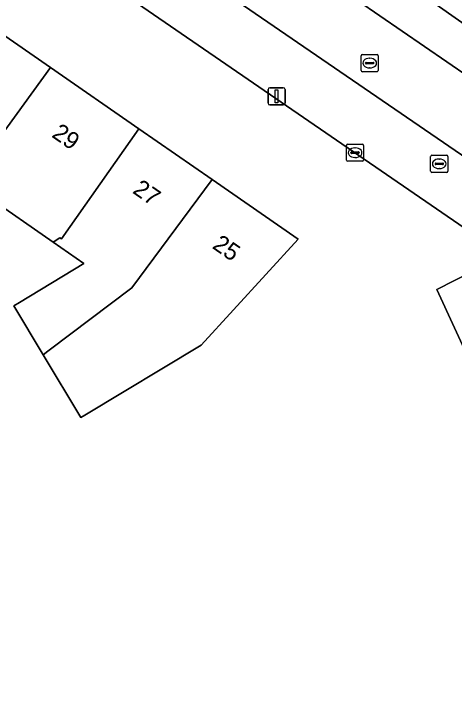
# Model space of a CAD drawing. Extents: x 163859 to 164644, y 379566 to 382155.
# Drawn here: x 164380.22 to 164405.83, y 381680.82 to 381721.32 of the extents above; entities that cross this region are included whole.
import ezdxf

# ---------------------------------------------------------------- set-up
doc = ezdxf.new("R2010")
doc.units = 0
for name, color, linetype in [('IMGEO_Brandkraan', 7, 'Continuous'), ('IMGEO_Erf', 7, 'Continuous'), ('IMGEO_Groenvoorziening', 7, 'Continuous'), ('IMGEO_Kolk', 7, 'Continuous'), ('IMGEO_Lichtmast', 7, 'Continuous'), ('IMGEO_Pand', 7, 'Continuous'), ('IMGEO_Pand_nummerreeks', 7, 'Continuous'), ('IMGEO_Parkeervlak_open', 7, 'Continuous'), ('IMGEO_Rijbaan_lokaal_gesloten', 7, 'Continuous'), ('IMGEO_Rioolput', 7, 'Continuous'), ('IMGEO_Waterloop', 7, 'Continuous')]:
    doc.layers.add(name, color=color, linetype=linetype)

msp = doc.modelspace()

# ---------------------------------------------------------------- linework, layer by layer
at = {"layer": 'IMGEO_Brandkraan'}
for p, q in [((164404.539, 381713.084), (164405.391, 381713.084)), ((164404.464, 381712.158), (164404.464, 381713.01)), ((164404.766, 381712.627), (164405.164, 381712.627)), ((164404.952, 381712.864), (164404.977, 381712.864)), ((164405.465, 381713.01), (164405.465, 381712.158)), ((164404.723, 381712.578), (164404.723, 381712.59)), ((164405.161, 381712.541), (164404.763, 381712.541)), ((164404.975, 381712.304), (164404.95, 381712.304)), ((164405.207, 381712.59), (164405.207, 381712.578)), ((164405.391, 381712.084), (164404.539, 381712.084))]:
    msp.add_line(p, q, dxfattribs=at)
for points in [[(164404.539, 381713.084), (164405.391, 381713.084)], [(164404.464, 381712.158), (164404.464, 381713.01)], [(164405.465, 381713.01), (164405.465, 381712.158)], [(164405.391, 381712.084), (164404.539, 381712.084)]]:
    msp.add_lwpolyline(points, dxfattribs=at)
for centre, radius, start, end in [((164404.541, 381713.008), 0.0765, 91.552, 178.448), ((164404.541, 381713.008), 0.0765, 91.552, 178.448), ((164405.389, 381713.008), 0.0765, 1.552, 88.448), ((164405.389, 381713.008), 0.0765, 1.552, 88.448), ((164404.763, 381712.587), 0.0403, 85.8775, 175.7526), ((164405.168, 381712.589), 0.0386, 1.7309, 96.639), ((164404.76, 381712.577), 0.0366, 178.938, 274.7102), ((164405.164, 381712.584), 0.043, 264.8664, 352.4533), ((164404.541, 381712.16), 0.0765, 181.552, 268.448), ((164404.541, 381712.16), 0.0765, 181.552, 268.448), ((164405.389, 381712.16), 0.0765, 271.552, 358.448), ((164405.389, 381712.16), 0.0765, 271.552, 358.448)]:
    msp.add_arc(centre, radius, start, end, dxfattribs=at)
for centre, major_axis, ratio, start_param, end_param in [((164404.951, 381712.584), (-0.387, 0.002), 0.722429, 4.712389, 7.853982), ((164404.976, 381712.584), (-0.39, 0.002), 0.717154, 1.570796, 4.712389)]:
    msp.add_ellipse(centre, major_axis=major_axis, ratio=ratio, start_param=start_param, end_param=end_param, dxfattribs=at)
at = {"layer": 'IMGEO_Erf'}
for points in [[(164404.83, 381705.266), (164406.925, 381706.323), (164406.418, 381708.86), (164381.892, 381725.724), (164366.579, 381736.251)], [(164378.015, 381721.193), (164382.346, 381718.188), (164387.477, 381714.627), (164391.751, 381711.661), (164396.75, 381708.192), (164391.116, 381702.026), (164384.351, 381697.949), (164384.116, 381697.807), (164381.927, 381701.462), (164380.218, 381704.316), (164380.541, 381704.511), (164384.291, 381706.771), (164382.491, 381708.022), (164378.587, 381710.736)], [(164441.086, 381626.391), (164437.24, 381634.76), (164435.396, 381638.772), (164432.979, 381644.03), (164418.395, 381675.757), (164404.83, 381705.266)]]:
    msp.add_lwpolyline(points, dxfattribs=at)
at = {"layer": 'IMGEO_Groenvoorziening'}
msp.add_lwpolyline([(164411.916, 381716.853), (164384.279, 381736.27), (164382.848, 381734.057), (164385.909, 381731.949), (164410.608, 381714.952), (164413.701, 381712.823)], dxfattribs=at)
msp.add_lwpolyline([(164412.893, 381702.27), (164411.398, 381704.132), (164411.007, 381703.551), (164410.636, 381702.998), (164408.971, 381700.556), (164406.531, 381702.22), (164408.196, 381704.662), (164408.255, 381704.621), (164408.629, 381705.166), (164406.925, 381706.323), (164404.83, 381705.266), (164418.395, 381675.757), (164430.172, 381690.536), (164429.462, 381691.018)], close=True, dxfattribs=at)
at = {"layer": 'IMGEO_Kolk'}
for p, q in [((164399.563, 381712.805), (164399.563, 381713.657)), ((164399.638, 381713.731), (164400.49, 381713.731)), ((164400.051, 381713.511), (164400.076, 381713.511)), ((164400.564, 381713.657), (164400.564, 381712.805)), ((164399.822, 381713.225), (164399.822, 381713.237)), ((164400.26, 381713.188), (164399.862, 381713.188)), ((164399.865, 381713.274), (164400.263, 381713.274)), ((164400.306, 381713.237), (164400.306, 381713.225)), ((164400.49, 381712.731), (164399.638, 381712.731)), ((164400.074, 381712.951), (164400.049, 381712.951))]:
    msp.add_line(p, q, dxfattribs=at)
for points in [[(164399.563, 381712.805), (164399.563, 381713.657)], [(164399.638, 381713.731), (164400.49, 381713.731)], [(164400.564, 381713.657), (164400.564, 381712.805)], [(164400.49, 381712.731), (164399.638, 381712.731)]]:
    msp.add_lwpolyline(points, dxfattribs=at)
for centre, radius, start, end in [((164399.64, 381713.655), 0.0765, 91.552, 178.448), ((164399.64, 381713.655), 0.0765, 91.552, 178.448), ((164400.488, 381713.655), 0.0765, 1.552, 88.448), ((164400.488, 381713.655), 0.0765, 1.552, 88.448), ((164399.862, 381713.234), 0.0403, 85.8775, 175.7526), ((164399.859, 381713.224), 0.0366, 178.938, 274.7102), ((164400.263, 381713.231), 0.043, 264.8664, 352.4533), ((164400.267, 381713.236), 0.0386, 1.7309, 96.639), ((164399.64, 381712.807), 0.0765, 181.552, 268.448), ((164399.64, 381712.807), 0.0765, 181.552, 268.448), ((164400.488, 381712.807), 0.0765, 271.552, 358.448), ((164400.488, 381712.807), 0.0765, 271.552, 358.448)]:
    msp.add_arc(centre, radius, start, end, dxfattribs=at)
for centre, major_axis, ratio, start_param, end_param in [((164400.05, 381713.231), (-0.387, 0.002), 0.722429, 4.712389, 7.853982), ((164400.075, 381713.231), (-0.39, 0.002), 0.717154, 1.570796, 4.712389)]:
    msp.add_ellipse(centre, major_axis=major_axis, ratio=ratio, start_param=start_param, end_param=end_param, dxfattribs=at)
at = {"layer": 'IMGEO_Lichtmast'}
for p, q in [((164395.001, 381716.114), (164395.001, 381716.914)), ((164395.001, 381716.914), (164395.001, 381716.114)), ((164395.101, 381717.014), (164395.891, 381717.014)), ((164395.891, 381717.014), (164395.101, 381717.014)), ((164395.991, 381716.914), (164395.991, 381716.114)), ((164395.991, 381716.114), (164395.991, 381716.914)), ((164395.891, 381716.014), (164395.101, 381716.014)), ((164395.101, 381716.014), (164395.891, 381716.014))]:
    msp.add_line(p, q, dxfattribs=at)
msp.add_lwpolyline([(164395.421, 381716.889), (164395.571, 381716.889), (164395.571, 381716.139), (164395.421, 381716.139), (164395.421, 381716.889)], dxfattribs=at)
for centre, start, end in [((164395.101, 381716.914), 90, 180), ((164395.101, 381716.914), 90, 180), ((164395.891, 381716.914), 0, 90), ((164395.891, 381716.914), 360, 90), ((164395.101, 381716.114), 180, 270), ((164395.101, 381716.114), 180, 270), ((164395.891, 381716.114), 270, 0), ((164395.891, 381716.114), 270, 0)]:
    msp.add_arc(centre, 0.1, start, end, dxfattribs=at)
at = {"layer": 'IMGEO_Pand'}
for points in [[(164369.371, 381711.799), (164372.95, 381707.902), (164375.31, 381709.792), (164375.391, 381709.7), (164377.736, 381711.844), (164382.346, 381718.188), (164378.015, 381721.193), (164373.447, 381714.819), (164373.349, 381714.887)], [(164387.477, 381714.627), (164382.346, 381718.188), (164377.736, 381711.844), (164375.391, 381709.7), (164376.254, 381708.729), (164378.587, 381710.736), (164382.491, 381708.022), (164382.888, 381708.27), (164382.979, 381708.208)], [(164391.751, 381711.661), (164387.477, 381714.627), (164382.979, 381708.208), (164382.888, 381708.27), (164382.491, 381708.022), (164384.291, 381706.771), (164380.541, 381704.511), (164380.218, 381704.316), (164381.927, 381701.462), (164382.194, 381701.664), (164382.275, 381701.725), (164387.087, 381705.358)], [(164396.75, 381708.192), (164391.751, 381711.661), (164387.087, 381705.358), (164382.275, 381701.725), (164382.194, 381701.664), (164381.927, 381701.462), (164384.116, 381697.807), (164384.351, 381697.949), (164391.116, 381702.026)]]:
    msp.add_lwpolyline(points, close=True, dxfattribs=at)
at = {"layer": 'IMGEO_Parkeervlak_open'}
msp.add_lwpolyline([(164352.536, 381750), (164324.768, 381769.068), (164324.32, 381768.391), (164323.62, 381767.407), (164322.896, 381766.247), (164346.556, 381750), (164366.579, 381736.251), (164381.892, 381725.724), (164406.418, 381708.86), (164407.122, 381709.878), (164407.816, 381710.901), (164408.346, 381711.663), (164383.72, 381728.586)], close=True, dxfattribs=at)
at = {"layer": 'IMGEO_Rijbaan_lokaal_gesloten'}
msp.add_lwpolyline([(164322.955, 381770.199), (164324.768, 381769.068), (164352.536, 381750), (164383.72, 381728.586), (164408.346, 381711.663), (164410.608, 381714.952), (164385.909, 381731.949), (164382.848, 381734.057), (164381.018, 381735.317), (164360.792, 381749.337), (164360.25, 381749.708), (164359.822, 381750), (164324.169, 381774.363)], dxfattribs=at)
at = {"layer": 'IMGEO_Rioolput'}
for p, q in [((164400.417, 381718.026), (164400.417, 381718.878)), ((164400.492, 381718.952), (164401.344, 381718.952)), ((164400.905, 381718.732), (164400.93, 381718.732)), ((164401.418, 381718.878), (164401.418, 381718.026)), ((164400.676, 381718.446), (164400.676, 381718.458)), ((164401.114, 381718.409), (164400.716, 381718.409)), ((164400.719, 381718.495), (164401.117, 381718.495)), ((164401.16, 381718.458), (164401.16, 381718.446)), ((164401.344, 381717.952), (164400.492, 381717.952)), ((164400.928, 381718.172), (164400.903, 381718.172))]:
    msp.add_line(p, q, dxfattribs=at)
for points in [[(164400.417, 381718.026), (164400.417, 381718.878)], [(164400.492, 381718.952), (164401.344, 381718.952)], [(164401.418, 381718.878), (164401.418, 381718.026)], [(164401.344, 381717.952), (164400.492, 381717.952)]]:
    msp.add_lwpolyline(points, dxfattribs=at)
for centre, radius, start, end in [((164400.494, 381718.876), 0.0765, 91.552, 178.448), ((164400.494, 381718.876), 0.0765, 91.552, 178.448), ((164401.342, 381718.876), 0.0765, 1.552, 88.448), ((164401.342, 381718.876), 0.0765, 1.552, 88.448), ((164400.716, 381718.455), 0.0403, 85.8775, 175.7526), ((164400.713, 381718.445), 0.0366, 178.938, 274.7102), ((164401.117, 381718.452), 0.043, 264.8664, 352.4533), ((164401.121, 381718.457), 0.0386, 1.7309, 96.639), ((164400.494, 381718.028), 0.0765, 181.552, 268.448), ((164400.494, 381718.028), 0.0765, 181.552, 268.448), ((164401.342, 381718.028), 0.0765, 271.552, 358.448), ((164401.342, 381718.028), 0.0765, 271.552, 358.448)]:
    msp.add_arc(centre, radius, start, end, dxfattribs=at)
for centre, major_axis, ratio, start_param, end_param in [((164400.904, 381718.452), (-0.387, 0.002), 0.722429, 4.712389, 7.853982), ((164400.929, 381718.452), (-0.39, 0.002), 0.717154, 1.570796, 4.712389)]:
    msp.add_ellipse(centre, major_axis=major_axis, ratio=ratio, start_param=start_param, end_param=end_param, dxfattribs=at)
at = {"layer": 'IMGEO_Waterloop'}
msp.add_lwpolyline([(164412.499, 381717.701), (164384.767, 381737.008), (164384.279, 381736.27), (164411.916, 381716.853), (164441.971, 381695.738), (164442.313, 381695.498), (164442.345, 381696.707)], close=True, dxfattribs=at)

# ---------------------------------------------------------------- texts
at = {"layer": 'IMGEO_Pand_nummerreeks'}
for s, rotation, p in [('29', 325.2415, (164382.362, 381714.184)), ('27', 325.2444, (164387.065, 381710.92)), ('25', 325.2444, (164391.701, 381707.703))]:
    msp.add_text(s, height=1, rotation=rotation, dxfattribs=at).set_placement(p)

doc.saveas('drawing.dxf')
